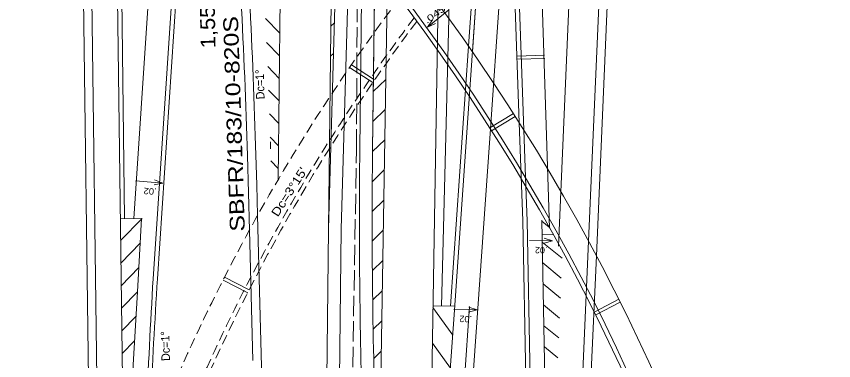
# Model space of a CAD drawing. Extents: x 2354993 to 2372084, y 6966390 to 6990057.
# Drawn here: x 2364180 to 2364948, y 6977227 to 6977552 of the extents above; entities that cross this region are included whole.
import ezdxf

# ---------------------------------------------------------------- set-up
doc = ezdxf.new("R2010")
doc.units = 0
doc.header["$LTSCALE"] = 3.2
doc.linetypes.add('LONG_DASHED', pattern=[7.5, 6, -1.5])
doc.linetypes.add('MEDIUM_DASHED', pattern=[4.5, 3, -1.5])
for name, color, linetype, lineweight in [('11', 7, 'Continuous', 13), ('12', 7, 'Continuous', 13), ('13', 7, 'Continuous', 13), ('19', 7, 'Continuous', 13), ('25', 7, 'Continuous', 13), ('30', 7, 'Continuous', 13), ('4', 7, 'Continuous', 13), ('5', 7, 'Continuous', 13)]:
    doc.layers.add(name, color=color, linetype=linetype, lineweight=lineweight)

msp = doc.modelspace()

# ---------------------------------------------------------------- linework, layer by layer
at = {"layer": '12'}
for p, q in [((2364676.136, 6977514.999), (2364650.151, 6977514.081)), ((2364676.242, 6977512.001), (2364650.257, 6977511.083)), ((2364514.605, 6977489.152), (2364492.873, 6977503.438)), ((2364516.307, 6977491.623), (2364494.575, 6977505.909)), ((2364646.876, 6977459.976), (2364624.664, 6977446.453)), ((2364648.436, 6977457.414), (2364626.224, 6977443.891)), ((2364397.038, 6977291.46), (2364373.884, 6977303.289)), ((2364398.4, 6977294.133), (2364375.246, 6977305.961)), ((2364745.82, 6977285.312), (2364722.816, 6977273.183)), ((2364747.219, 6977282.658), (2364724.215, 6977270.529))]:
    msp.add_line(p, q, dxfattribs=at)
at = {"layer": '19'}
for p, q in [((2364565.952, 6977541.376), (2364570.736, 6977548.173)), ((2364317.267, 6977394.658), (2364309.126, 6977392.982)), ((2364683.737, 6977340.26), (2364675.71, 6977338.1)), ((2364612.746, 6977275.44), (2364604.719, 6977273.28))]:
    msp.add_line(p, q, dxfattribs=at)
for points in [[(2364586.002, 6977557.585), (2364565.952, 6977541.376), (2364573.594, 6977544.629)], [(2364291.557, 6977396.58), (2364317.267, 6977394.658), (2364309.471, 6977397.522)], [(2364661.815, 6977340.58), (2364683.737, 6977340.26), (2364675.782, 6977342.652)], [(2364590.824, 6977275.76), (2364612.746, 6977275.44), (2364604.791, 6977277.832)]]:
    msp.add_lwpolyline(points, dxfattribs=at)
at = {"layer": '25'}
msp.add_line((2364308.187, 6977304.651), (2364340.403, 6977788.872), dxfattribs=at)
msp.add_arc((2372851.201, 6976799.233), 8557.951, 176.61424, 178.30543, dxfattribs=at)
at = {"layer": '30'}
msp.add_line((2364514.461, 6977426.009), (2364514.46, 6977426.009), dxfattribs=at)
at = {"layer": '4'}
for p in [(2364642.388, 6977692.091), (2364592.679, 6976978.427)]:
    msp.add_line(p, (2364625.192, 6977445.625), dxfattribs=at)
msp.add_lwpolyline([(2364586.065, 6977549.629), (2364586.993, 6977628.202), (2364591.132, 6977978.904)], dxfattribs=at)
msp.add_arc((2358034.476, 6977244.063), 6386.72, 1.64074, 1.69802, dxfattribs=at)
at = {"layer": '5'}
for p, q in [((2364250.238, 6976989.323), (2364238.582, 6977875.031)), ((2364246.695, 6977868.679), (2364257.91, 6977015.279)), ((2364280.781, 6977100.108), (2364270.924, 6977849.204)), ((2364281.346, 6977361.167), (2364274.986, 6977844.567)), ((2364689.178, 6977335.168), (2364707.646, 6977760.094)), ((2364724.81, 6977326.163), (2364743.625, 6977758.845)), ((2364717.405, 6977340.009), (2364734.731, 6977738.457)), ((2364485.08, 6977351.259), (2364495.752, 6977726.05)), ((2364502.462, 6977426.131), (2364506.001, 6977726.13)), ((2364514.46, 6977426.009), (2364518, 6977725.988)), ((2364652.368, 6977451.315), (2364643.799, 6977693.64)), ((2364591.636, 6977279.587), (2364619.625, 6977681.868)), ((2364658.49, 6977391.403), (2364648.972, 6977660.539)), ((2364428.294, 6977627.07), (2364425.729, 6977397.952)), ((2364608.26, 6977518.156), (2364615.452, 6977621.75)), ((2364518.585, 6976988.524), (2364528.853, 6977616.591)), ((2364565.082, 6976896.195), (2364576.847, 6977615.806)), ((2364289.908, 6977361.289), (2364303.857, 6977570.955)), ((2364427.27, 6977535.569), (2364413.774, 6977549.372)), ((2364579.253, 6977278.831), (2364586.065, 6977549.629)), ((2364475.334, 6977542.268), (2364478.605, 6977545.463)), ((2364427.033, 6977514.357), (2364414.856, 6977526.81)), ((2364587.627, 6977278.696), (2364604.616, 6977523.417)), ((2364475.001, 6977513.985), (2364477.786, 6977516.706)), ((2364426.796, 6977493.145), (2364415.844, 6977504.344)), ((2364515.106, 6977480.778), (2364526.82, 6977492.219)), ((2364426.558, 6977471.934), (2364416.742, 6977481.97)), ((2364514.773, 6977452.496), (2364526.356, 6977463.809)), ((2364426.319, 6977450.722), (2364417.548, 6977459.692)), ((2364655.632, 6977359.023), (2364652.368, 6977451.315)), ((2364426.082, 6977429.509), (2364418.081, 6977437.691)), ((2364514.44, 6977424.215), (2364525.891, 6977435.399)), ((2364398.641, 6977350.205), (2364396.773, 6977420.626)), ((2364405.509, 6977392.943), (2364404.742, 6977420.845)), ((2364425.844, 6977408.298), (2364418.837, 6977415.464)), ((2364514.297, 6977396.119), (2364525.427, 6977406.99)), ((2364406.277, 6977364.018), (2364405.509, 6977392.943)), ((2364659.63, 6977359.164), (2364658.49, 6977391.403)), ((2364514.27, 6977368.136), (2364524.962, 6977378.58)), ((2364411.249, 6977176.688), (2364406.277, 6977364.018)), ((2364277.347, 6977361.111), (2364297.345, 6977361.394)), ((2364277.618, 6977340.505), (2364297.932, 6977361.405)), ((2364655.625, 6977359.311), (2364666.287, 6976808.765)), ((2364659.624, 6977359.388), (2364670.286, 6976808.842)), ((2364673.621, 6977359.659), (2364679.974, 6977031.633)), ((2364673.637, 6977358.831), (2364680.458, 6977353.235)), ((2364401.898, 6977227.486), (2364398.641, 6977350.205)), ((2364463.051, 6976501.012), (2364473.085, 6977351.601)), ((2364468.806, 6975971.515), (2364485.084, 6977351.459)), ((2364514.242, 6977340.154), (2364524.498, 6977350.169)), ((2364673.484, 6977345.842), (2364684.368, 6977346.22)), ((2364277.898, 6977319.276), (2364296.396, 6977338.304)), ((2364674.019, 6977339.116), (2364692.678, 6977323.807)), ((2364683.134, 6976551.86), (2364717.405, 6977340.009)), ((2364690.072, 6976527.283), (2364724.81, 6977326.163)), ((2364514.283, 6977312.237), (2364524.033, 6977321.76)), ((2364674.401, 6977319.401), (2364691.864, 6977305.074)), ((2364278.176, 6977298.048), (2364294.858, 6977315.206)), ((2364674.782, 6977299.686), (2364691.049, 6977286.34)), ((2364278.456, 6977276.813), (2364293.339, 6977292.123)), ((2364514.717, 6977284.705), (2364523.569, 6977293.35)), ((2364565.082, 6976896.195), (2364591.695, 6977279.547)), ((2364675.164, 6977279.971), (2364690.235, 6977267.607)), ((2364571.23, 6977277.458), (2364589.757, 6977251.624)), ((2364571.254, 6977278.96), (2364591.632, 6977278.632)), ((2364574.032, 6976822.971), (2364605.662, 6977278.577)), ((2364278.735, 6977255.585), (2364291.909, 6977269.136)), ((2364515.151, 6977257.172), (2364523.104, 6977264.94)), ((2364675.546, 6977260.257), (2364689.42, 6977248.873)), ((2364279.015, 6977234.351), (2364290.579, 6977246.246)), ((2364570.688, 6977243.894), (2364587.585, 6977220.334)), ((2364515.585, 6977229.64), (2364522.64, 6977236.53)), ((2364675.928, 6977240.541), (2364688.605, 6977230.139))]:
    msp.add_line(p, q, dxfattribs=at)
at = {"layer": '5', "linetype": 'LONG_DASHED'}
for p, q in [((2364499.337, 6977426.187), (2364500.596, 6977726.327)), ((2364483.383, 6976501.515), (2364499.337, 6977426.187))]:
    msp.add_line(p, q, dxfattribs=at)
at = {"layer": '5'}
for points in [[(2364680.862, 6977352.125), (2364668.863, 6977720.558), (2364659.733, 6977978.756)], [(2364312.181, 6977304.414), (2364329.909, 6977570.868), (2364344.181, 6977785.387)], [(2364514.46, 6977426.009), (2364518, 6977725.988), (2364514.46, 6977426.009)], [(2364604.616, 6977523.417), (2364611.079, 6977616.516), (2364615.635, 6977682.143)], [(2364297.345, 6977361.394), (2364293.339, 6977292.123), (2364289.347, 6977223.458), (2364285.358, 6977133.277), (2364282.372, 6976979.158)]]:
    msp.add_lwpolyline(points, dxfattribs=at)
msp.add_lwpolyline([(2364473.085, 6977351.601), (2364483.757, 6977726.392), (2364477.507, 6977726.466)], close=True, dxfattribs=at)
for centre, radius, start, end in [((2363217.727, 6979240.251), 1692, 268.21361, 306.66787), ((2358691.326, 6977263.63), 5707.578, 1.57563, 4.53232), ((2358691.326, 6977263.63), 5715.578, 1.57563, 4.53232), ((2363030.028, 6976428.641), 1917.859, 350.16881, 38.12295), ((2363030.028, 6976428.641), 1891.859, 350.16881, 38.12295), ((2363030.028, 6976428.641), 1895.859, 350.16881, 38.12295), ((2370231.641, 6977358.541), 5729.578, 179.32409, 181.97449), ((2370231.641, 6977358.541), 5717.578, 179.32409, 182.18622), ((2373046.888, 6976763.367), 8751.449, 176.45552, 178.03092)]:
    msp.add_arc(centre, radius, start, end, dxfattribs=at)
at = {"layer": '5', "linetype": 'MEDIUM_DASHED'}
for centre, radius, start, end in [((2365952.337, 6976500.333), 1770.947, 142.90202, 179.54796), ((2365952.338, 6976500.332), 1748.947, 143.1115, 179.53746), ((2365952.338, 6976500.332), 1744.947, 143.1512, 179.53746)]:
    msp.add_arc(centre, radius, start, end, dxfattribs=at)

# ---------------------------------------------------------------- texts
at = {"layer": '11', "width": 1.05}
for p in [(2364678.919, 6977334.263), (2364607.928, 6977269.443)]:
    msp.add_text('.02', height=6, rotation=178.117, dxfattribs=at).set_placement(p)
at = {"layer": '12'}
for s, height, rotation, width, p in [('Dc=1°', 8, 91.467, 0.95, (2364412.928, 6977473.499)), ("Dc=3°15'", 7.999, 57.39, 1.2, (2364425.361, 6977362.211)), ('Dc=1°', 8, 91.467, 0.95, (2364324.054, 6977227.257))]:
    msp.add_text(s, height=height, rotation=rotation, dxfattribs=dict(at, width=width)).set_placement(p)
at = {"layer": '13'}
for s, rotation, width, p in [('1,554', 91.067, 1.1, (2364366.84, 6977521.589)), ('SBFR/183/10-820S', 91.849, 1.25, (2364394.43, 6977349.116))]:
    msp.add_text(s, height=14, rotation=rotation, dxfattribs=dict(at, width=width)).set_placement(p)
at = {"layer": '19'}
for s, rotation, width, p in [('.045', 35.983, 1.45, (2364565.45, 6977544.224)), ('.02', 176.461, 1.1, (2364311.68, 6977389.487))]:
    msp.add_text(s, height=6, rotation=rotation, dxfattribs=dict(at, width=width)).set_placement(p)

doc.saveas('drawing.dxf')
